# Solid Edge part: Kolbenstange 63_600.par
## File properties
Username: ahadarics
Dokumentum tartalom típus: 0
Author: ahadarics
Last saved by: ahadarics
Revision: 93
Sűrűség: 0,000 kg/m^3
Pontosság: 0,990
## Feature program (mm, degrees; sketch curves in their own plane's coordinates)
base feature "unnamed BaseFeature 1"
thread "unnamed Thread 1"
chamfer "Letörés_1"  SetBackValue2 = 20 deg
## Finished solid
Body 1: solid body, 20 faces, 31 edges, 14 vertices.
  Faces by surface: plane 8, cylinder 5, torus 4, cone 3
  Edges by curve: circle 16, line 9, curve on surface 4, ellipse 2
Bounding box of the edges (mm; curved faces can reach further): 63.000 x 63.000 x 756.500, from (-31.5, -31.5, -70.75) to (31.5, 31.5, 685.75).
Cylindrical faces by radius (mm): R6.75 x1, R8 x1, R9.75 x1, R10 x1, R31.5 x1
Conical faces (half-angle, radius in mm at the cone's reference point): 20 deg R8 x1, 30 deg R9.875 x1, 60 deg R7.375 x1
Toroidal faces (ring radius, tube radius in mm): R7.15 r0.4 x2, R8.55 r1.2 x2
Planar faces by outward normal: +x 1, +z 3, -x 1, -z 1, oblique 2
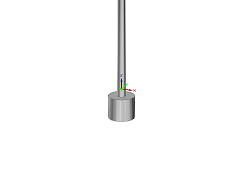
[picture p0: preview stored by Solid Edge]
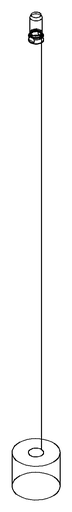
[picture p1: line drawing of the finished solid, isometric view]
